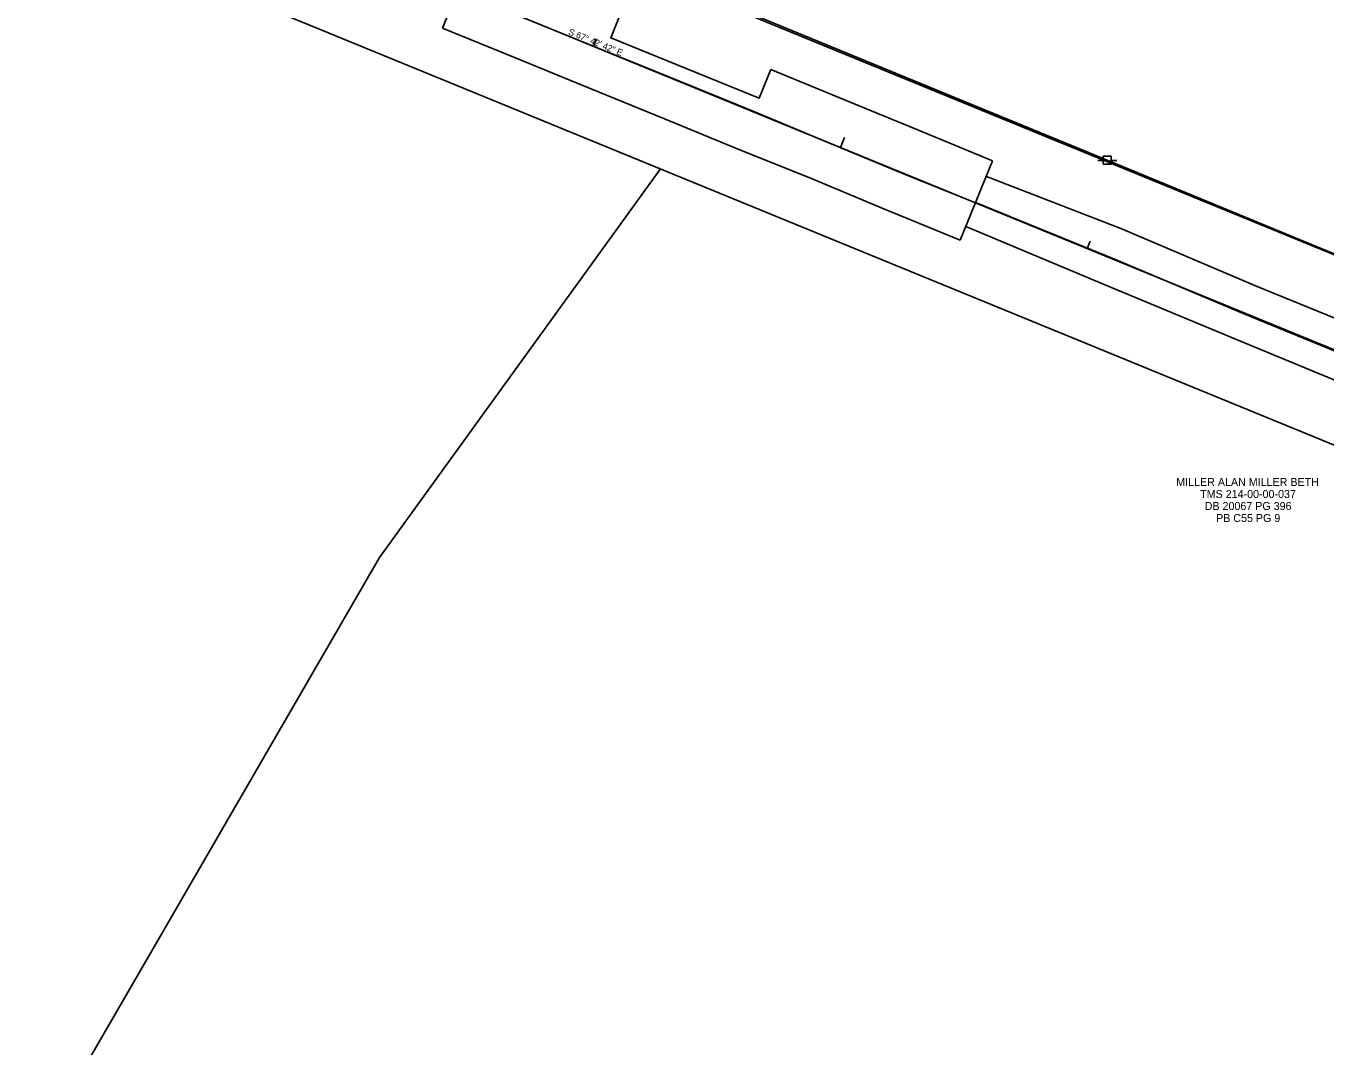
# Model space of a CAD drawing. Extents: x 1903662 to 1907233, y 1108998 to 1112872.
# Drawn here: x 1905330.5 to 1905817.9, y 1109706.1 to 1110088.7 of the extents above; entities that cross this region are included whole.
import ezdxf

# ---------------------------------------------------------------- set-up
doc = ezdxf.new("R2010")
doc.units = 0
for name, color, linetype in [('RD_DTM_BkLn1', 7, 'Continuous'), ('RD_EX_Bridge', 7, 'Continuous'), ('RD_EX_DV_Prop', 7, 'Continuous'), ('RD_EX_DV_TX_Prop', 7, 'Continuous'), ('RD_EX_Road', 7, 'Continuous'), ('RD_EX_RW', 7, 'Continuous'), ('RD_EX_UT', 7, 'Continuous'), ('RD_HC_Cl', 7, 'Continuous'), ('RD_HC_Data', 7, 'Continuous'), ('RD_HC_Data_Tic', 7, 'Continuous'), ('SV_Plan_Bridge', 7, 'Continuous'), ('SV_UT_Electric_Lines', 7, 'Continuous')]:
    doc.layers.add(name, color=color, linetype=linetype)

msp = doc.modelspace()

# ---------------------------------------------------------------- linework, layer by layer
at = {"layer": 'RD_DTM_BkLn1'}
for points in [[(1904865.19, 1110359), (1904913.1, 1110339.8), (1904961.42, 1110320.08), (1905008.53, 1110300.58), (1905058.58, 1110280.34), (1905106.3, 1110260.53), (1905156.09, 1110239.84), (1905206.21, 1110219.59), (1905254.3, 1110199.45), (1905300.11, 1110180.14), (1905347.21, 1110160.98), (1905395.33, 1110141.42), (1905443.75, 1110121.81), (1905492.46, 1110101.83), (1905520.15, 1110090.53), (1905547.72, 1110079.36), (1905575.52, 1110068.04), (1905603.32, 1110056.68), (1905630.91, 1110045.24), (1905658.56, 1110033.72), (1905686.41, 1110022.54)], [(1905686.48, 1110022.61), (1905738.58, 1110001.31), (1905787.5, 1109980.72), (1905836.79, 1109960.49), (1905886.09, 1109940.06), (1905933.61, 1109920.5), (1905982.43, 1109901.08), (1906031.95, 1109880.93), (1906079.41, 1109861.63), (1906128.68, 1109841.73), (1906173.54, 1109823.42), (1906221.88, 1109803.54)]]:
    msp.add_lwpolyline(points, dxfattribs=at)
at = {"layer": 'RD_EX_Bridge'}
for p, q in [((1905486.65, 1110087.88), (1905498.73, 1110117.73)), ((1905680.72, 1110008.45), (1905692.79, 1110038.24))]:
    msp.add_line(p, q, dxfattribs=at)
for points in [[(1905554.05, 1110094.99), (1905549.7, 1110084.36), (1905578.01, 1110072.79), (1905605.31, 1110061.65), (1905609.79, 1110072.39)], [(1905680.72, 1110008.45), (1905652.97, 1110019.9), (1905625.29, 1110031.43), (1905597.48, 1110042.64), (1905569.85, 1110054), (1905541.95, 1110065.28), (1905514.28, 1110076.68), (1905486.65, 1110087.88)], [(1905692.79, 1110038.24), (1905665.05, 1110049.68), (1905637.37, 1110061.08), (1905609.79, 1110072.39)]]:
    msp.add_lwpolyline(points, dxfattribs=at)
at = {"layer": 'RD_EX_DV_Prop'}
msp.add_lwpolyline([(1906134.79, 1109803.04), (1906085.04, 1109681.02), (1905972.27, 1109733.72), (1905818.66, 1109681.58), (1905711.89, 1109606.46), (1905677.41, 1109545.61), (1905342.86, 1109682.01), (1905463.07, 1109889.61), (1905568.32, 1110035.23)], dxfattribs=at)
at = {"layer": 'RD_EX_Road'}
for points in [[(1905690.58, 1110032.38), (1905740.94, 1110012.84), (1905792.12, 1109991.14), (1905841.47, 1109970.96), (1905889.9, 1109950.42), (1905938.3, 1109930.68), (1905985.99, 1109911.49), (1906036.2, 1109891.33), (1906083.57, 1109872.1), (1906132.15, 1109852.67), (1906178.06, 1109834.09), (1906226.28, 1109814.29)], [(1905682.83, 1110013.58), (1905734.66, 1109991.82), (1905783.64, 1109971.5), (1905833.5, 1109950.95), (1905881.99, 1109930.52), (1905929.54, 1109910.92), (1905978.23, 1109891.27), (1906027.19, 1109871.52), (1906075.16, 1109852.25), (1906125.33, 1109832.56), (1906169.72, 1109814.29), (1906218.45, 1109794.17)]]:
    msp.add_lwpolyline(points, dxfattribs=at)
at = {"layer": 'RD_EX_RW'}
for p, q in [((1904864.32, 1110395.12), (1906497.97, 1109725.51)), ((1904839.26, 1110334.07), (1906209.37, 1109772.47))]:
    msp.add_line(p, q, dxfattribs=at)
at = {"layer": 'RD_EX_UT'}
for p, q in [((1905732.3, 1110038.4), (1905734.35, 1110038.4)), ((1905735.85, 1110038.44), (1905735.85, 1110038.44)), ((1905737.35, 1110038.4), (1905739.5, 1110038.4))]:
    msp.add_line(p, q, dxfattribs=at)
msp.add_lwpolyline([(1904589.73, 1110482.88), (1904891.43, 1110385.65), (1905171.11, 1110270.76), (1905436.6, 1110161.49), (1905735.85, 1110038.44), (1905992.24, 1109932.67), (1906258.29, 1109823.17), (1906443.47, 1109747.31)], dxfattribs=at)
msp.add_lwpolyline([(1905734.35, 1110036.94), (1905734.36, 1110039.94), (1905737.35, 1110039.94), (1905737.35, 1110036.94)], close=True, dxfattribs=at)
at = {"layer": 'RD_HC_Cl'}
msp.add_line((1904865.19, 1110359.1), (1906221.88, 1109803.01), dxfattribs=at)
at = {"layer": 'RD_HC_Data_Tic'}
for p, q in [((1905543.27, 1110081.17), (1905544.4, 1110083.94)), ((1905635.8, 1110043.24), (1905637.31, 1110046.94)), ((1905728.32, 1110005.31), (1905729.46, 1110008.09))]:
    msp.add_line(p, q, dxfattribs=at)
at = {"layer": 'SV_Plan_Bridge'}
for points in [[(1905680.72, 1110008.45), (1905652.97, 1110019.9), (1905625.29, 1110031.43), (1905597.48, 1110042.64), (1905569.85, 1110054), (1905541.95, 1110065.28), (1905514.28, 1110076.68), (1905486.65, 1110087.88)], [(1905692.79, 1110038.24), (1905665.05, 1110049.68), (1905637.37, 1110061.08), (1905609.79, 1110072.39)]]:
    msp.add_lwpolyline(points, dxfattribs=at)
at = {"layer": 'SV_UT_Electric_Lines'}
msp.add_lwpolyline([(1904589.73, 1110482.88), (1904891.43, 1110385.65), (1905171.11, 1110270.76), (1905436.6, 1110161.49), (1905735.85, 1110038.44), (1905992.24, 1109932.67), (1906258.29, 1109823.17), (1906443.47, 1109747.31)], dxfattribs=at)

# ---------------------------------------------------------------- texts
at = {"layer": 'RD_EX_DV_TX_Prop'}
for s, p in [('MILLER ALAN MILLER BETH', (1905761.72, 1109916.37)), ('TMS 214-00-00-037', (1905770.69, 1109911.87)), ('DB 20067 PG 396', (1905772.39, 1109907.37)), ('PB C55 PG 9', (1905776.66, 1109902.87))]:
    msp.add_text(s, height=3, dxfattribs=at).set_placement(p)
at = {"layer": 'RD_HC_Data'}
msp.add_text('S 67%%d 42\' 42" E', height=2.4, rotation=337.7118, dxfattribs=at).set_placement((1905533.64, 1110085.65))

doc.saveas('drawing.dxf')
